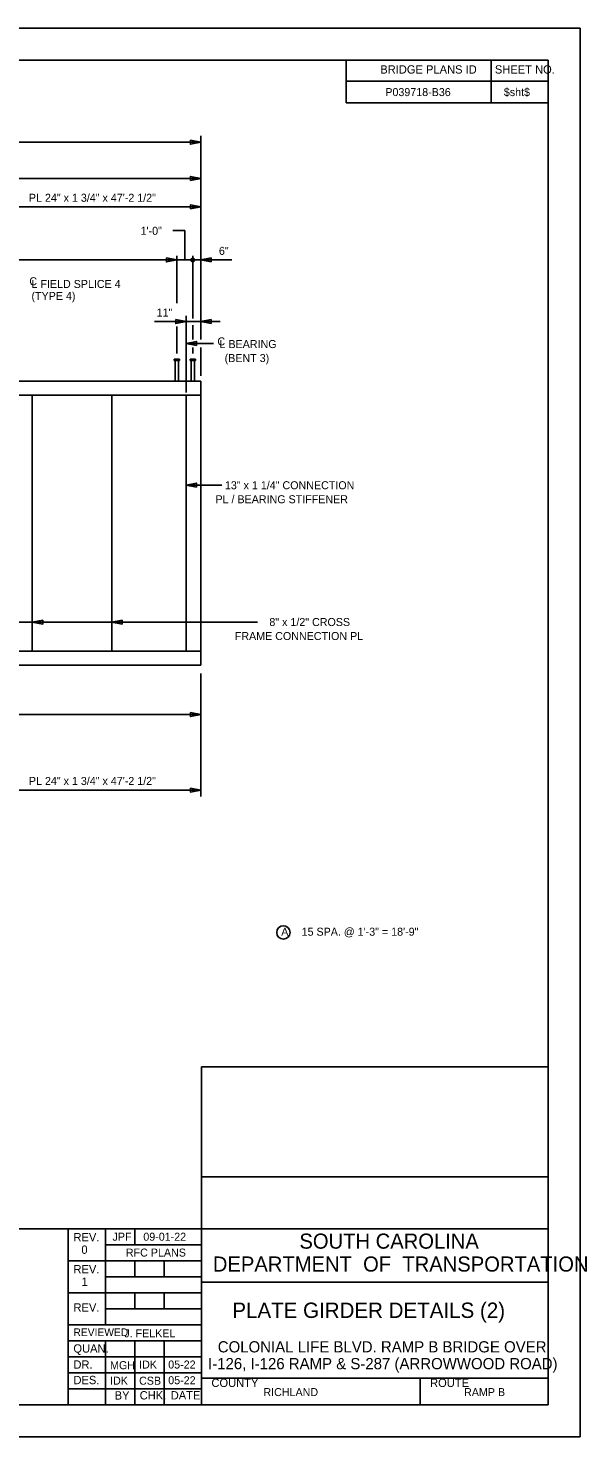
# Model space of a CAD drawing. Extents: x -305 to -161, y -187 to -99.
# Drawn here: x -195.7 to -160.8, y -187.5 to -99.5 of the extents above; entities that cross this region are included whole.
import ezdxf

# ---------------------------------------------------------------- set-up
doc = ezdxf.new("R2010")
doc.units = 0
for name, color, linetype in [('BR_AUTO DIMENSION', 7, 'Continuous'), ('BR_BORDER LINES', 7, 'Continuous'), ('BR_CENTER LINES', 7, 'Continuous'), ('BR_STRUCTURAL STEEL', 7, 'Continuous'), ('BR_TEXT', 7, 'Continuous'), ('Default', 7, 'Continuous'), ('Level 31', 7, 'Continuous')]:
    doc.layers.add(name, color=color, linetype=linetype)

msp = doc.modelspace()

# ---------------------------------------------------------------- linework, layer by layer
at = {"layer": 'BR_AUTO DIMENSION'}
for p, q in [((-184.885, -118.929), (-184.885, -106.206)), ((-284.516, -106.618), (-184.885, -106.618)), ((-231.124, -108.876), (-184.885, -108.876)), ((-184.885, -110.653), (-197.374, -110.653)), ((-225.281, -113.971), (-186.385, -113.971)), ((-186.385, -116.668), (-186.385, -113.71)), ((-182.932, -113.971), (-186.385, -113.971)), ((-185.385, -117.621), (-185.385, -113.71)), ((-187.771, -117.821), (-183.662, -117.821)), ((-186.385, -119.81), (-186.385, -118.124)), ((-185.385, -118.929), (-185.385, -118.048)), ((-185.802, -119.183), (-184.078, -119.183)), ((-185.385, -119.81), (-185.385, -119.447)), ((-184.885, -121.218), (-184.885, -119.447)), ((-185.802, -128.037), (-183.576, -128.037)), ((-225.147, -136.601), (-181.335, -136.601)), ((-184.885, -139.795), (-184.885, -147.486)), ((-184.885, -142.367), (-219.624, -142.367)), ((-197.374, -147.085), (-184.885, -147.085))]:
    msp.add_line(p, q, dxfattribs=at)
for points in [[(-185.535, -106.493), (-184.885, -106.618), (-185.535, -106.743)], [(-185.535, -109.001), (-184.885, -108.876), (-185.535, -108.751)], [(-185.535, -110.778), (-184.885, -110.653), (-185.535, -110.528)], [(-187.035, -113.846), (-186.385, -113.971), (-187.035, -114.096)], [(-184.235, -114.096), (-184.885, -113.971), (-184.235, -113.846)], [(-186.452, -117.696), (-185.802, -117.821), (-186.452, -117.946)], [(-184.235, -117.946), (-184.885, -117.821), (-184.235, -117.696)], [(-185.152, -119.308), (-185.802, -119.183), (-185.152, -119.058)], [(-185.152, -128.162), (-185.802, -128.037), (-185.152, -127.912)], [(-194.766, -136.726), (-195.416, -136.601), (-194.766, -136.476)], [(-189.803, -136.726), (-190.453, -136.601), (-189.803, -136.476)], [(-185.535, -142.242), (-184.885, -142.367), (-185.535, -142.492)], [(-185.535, -146.96), (-184.885, -147.085), (-185.535, -147.21)]]:
    msp.add_lwpolyline(points, close=True, dxfattribs=at)
msp.add_lwpolyline([(-185.885, -113.971), (-185.885, -112.129), (-186.625, -112.129)], dxfattribs=at)
for centre, radius in [((-185.385, -113.971), 0.111), ((-179.72, -155.982), 0.417)]:
    msp.add_circle(centre, radius, dxfattribs=at)
at = {"layer": 'BR_BORDER LINES'}
for p, q in [((-163.178, -101.489), (-297.843, -101.489)), ((-175.788, -104.156), (-175.788, -101.489)), ((-166.722, -104.156), (-166.722, -101.489)), ((-163.178, -185.489), (-163.178, -101.489)), ((-175.788, -102.808), (-163.178, -102.808)), ((-166.722, -102.808), (-163.178, -102.808)), ((-163.178, -104.156), (-175.788, -104.156)), ((-184.846, -185.489), (-184.846, -164.383)), ((-184.846, -164.383), (-163.178, -164.383)), ((-184.845, -171.242), (-163.178, -171.242)), ((-214.64, -174.489), (-193.18, -174.489)), ((-193.18, -185.489), (-193.18, -174.489)), ((-193.18, -174.489), (-163.178, -174.489)), ((-190.846, -174.489), (-190.846, -180.489)), ((-189.013, -175.489), (-189.013, -174.489)), ((-190.846, -175.489), (-184.846, -175.489)), ((-193.18, -176.489), (-184.846, -176.489)), ((-189.013, -177.489), (-189.013, -176.489)), ((-187.179, -177.489), (-187.179, -176.489)), ((-190.846, -177.489), (-184.846, -177.489)), ((-193.18, -178.489), (-184.846, -178.489)), ((-189.013, -179.489), (-189.013, -178.489)), ((-187.179, -179.489), (-187.179, -178.489)), ((-184.846, -177.822), (-184.846, -177.822)), ((-184.846, -177.823), (-163.178, -177.823)), ((-190.846, -179.489), (-184.846, -179.489)), ((-193.18, -180.489), (-184.846, -180.489)), ((-193.18, -181.489), (-184.846, -181.489)), ((-190.846, -181.489), (-190.846, -185.489)), ((-189.013, -181.489), (-189.013, -185.489)), ((-187.179, -181.489), (-187.179, -185.489)), ((-193.18, -182.489), (-184.846, -182.489)), ((-193.18, -183.489), (-184.846, -183.489)), ((-184.846, -183.823), (-163.178, -183.823)), ((-184.456, -183.823), (-163.178, -183.823)), ((-171.179, -185.489), (-171.179, -183.823)), ((-193.18, -184.489), (-184.846, -184.489)), ((-297.843, -185.489), (-163.178, -185.489))]:
    msp.add_line(p, q, dxfattribs=at)
at = {"layer": 'BR_CENTER LINES'}
msp.add_line((-185.802, -117.463), (-185.802, -122.256), dxfattribs=at)
at = {"layer": 'BR_STRUCTURAL STEEL'}
for p, q in [((-184.885, -121.537), (-197.374, -121.537)), ((-184.885, -121.537), (-184.885, -122.412)), ((-184.885, -122.412), (-284.516, -122.412)), ((-195.416, -138.412), (-195.416, -122.412)), ((-190.453, -138.412), (-190.453, -122.412)), ((-185.802, -122.412), (-185.802, -138.412)), ((-184.885, -122.412), (-184.885, -138.412)), ((-184.885, -138.412), (-284.516, -138.412)), ((-184.885, -138.412), (-184.885, -139.287)), ((-184.885, -139.287), (-197.374, -139.287))]:
    msp.add_line(p, q, dxfattribs=at)
at = {"layer": 'Default'}
for p, q in [((-186.557, -120.162), (-186.557, -120.256)), ((-186.557, -120.162), (-186.213, -120.162)), ((-186.557, -120.256), (-186.213, -120.256)), ((-186.494, -120.256), (-186.494, -121.537)), ((-186.276, -120.256), (-186.276, -121.537)), ((-186.213, -120.162), (-186.213, -120.256)), ((-185.557, -120.162), (-185.557, -120.256)), ((-185.557, -120.162), (-185.213, -120.162)), ((-185.557, -120.256), (-185.213, -120.256)), ((-185.494, -120.256), (-185.494, -121.537)), ((-185.276, -120.256), (-185.276, -121.537)), ((-185.213, -120.162), (-185.213, -120.256))]:
    msp.add_line(p, q, dxfattribs=at)
at = {"layer": 'Level 31'}
msp.add_line((-174.011, -179.583), (-174.011, -179.583), dxfattribs=at)
msp.add_lwpolyline([(-305.176, -187.489), (-161.176, -187.489), (-161.176, -99.489), (-305.176, -99.489)], close=True, dxfattribs=at)

# ---------------------------------------------------------------- texts
at = {"layer": 'BR_AUTO DIMENSION'}
for s, p in [('PL 24" x 1 3/4" x 47\'-2 1/2"', (-195.627, -110.334)), ('1\'-0"', (-188.647, -112.398)), ('6"', (-183.75, -113.652)), ('11"', (-187.644, -117.502)), ('PL 24" x 1 3/4" x 47\'-2 1/2"', (-195.627, -146.766)), ('A', (-179.854, -156.185)), ('15 SPA. @ 1\'-3" = 18\'-9"', (-178.579, -156.185))]:
    msp.add_text(s, height=0.5, rotation=360, dxfattribs=at).set_placement(p)
at = {"layer": 'BR_TEXT'}
for s, height, p in [('BRIDGE PLANS ID', 0.52, (-173.663, -102.327)), ('SHEET NO.', 0.52, (-166.499, -102.327)), ('P039718-B36', 0.5, (-173.348, -103.732)), ('$sht$', 0.5, (-165.939, -103.732)), ('C', 0.5, (-183.843, -119.306)), ('L BEARING', 0.5, (-183.711, -119.473)), ('(BENT 3)', 0.5, (-183.392, -120.348)), ('13" x 1 1/4" CONNECTION ', 0.5, (-183.374, -128.293)), ('PL / BEARING STIFFENER', 0.5, (-183.966, -129.168)), ('8" x 1/2" CROSS ', 0.5, (-180.596, -136.838)), ('FRAME CONNECTION PL', 0.5, (-182.757, -137.713)), ('REV.', 0.52, (-192.841, -175.277)), ('JPF', 0.5, (-190.4, -175.239)), ('09-01-22', 0.5, (-188.475, -175.239)), ('SOUTH CAROLINA', 0.94348, (-178.718, -175.735)), ('0', 0.52, (-192.345, -176.057)), ('RFC PLANS', 0.5, (-189.566, -176.229)), ('REV.', 0.52, (-192.841, -177.277)), ('DEPARTMENT  OF  TRANSPORTATION', 0.94348, (-184.129, -177.166)), ('1', 0.52, (-192.337, -178.057)), ('REV.', 0.52, (-192.841, -179.667)), ('PLATE GIRDER DETAILS (2)', 0.96, (-182.913, -180.063)), ('REVIEWED', 0.48, (-192.843, -181.195)), ('J. FELKEL', 0.5, (-189.664, -181.272)), ('QUAN.', 0.52, (-192.846, -182.229)), ('COLONIAL LIFE BLVD. RAMP B BRIDGE OVER', 0.7, (-183.82, -182.216)), ('DR.', 0.52, (-192.845, -183.235)), ('MGH', 0.5, (-190.555, -183.263)), ('IDK', 0.5, (-188.739, -183.222)), ('05-22', 0.5, (-186.918, -183.222)), ('I-126, I-126 RAMP & S-287 (ARROWWOOD ROAD) ', 0.7, (-184.429, -183.266)), ('DES.', 0.52, (-192.841, -184.2)), ('IDK', 0.5, (-190.555, -184.228)), ('CSB', 0.5, (-188.739, -184.234)), ('05-22', 0.5, (-186.918, -184.203)), ('COUNTY', 0.52, (-184.217, -184.376)), ('ROUTE', 0.52, (-170.55, -184.376)), ('BY', 0.52, (-190.265, -185.161)), ('CHK.', 0.52, (-188.701, -185.156)), ('DATE', 0.52, (-186.761, -185.156)), ('RICHLAND', 0.5, (-180.968, -184.944)), ('RAMP B', 0.5, (-168.424, -184.944))]:
    msp.add_text(s, height=height, dxfattribs=at).set_placement(p)
for s, p in [('C', (-195.601, -115.551)), ('L FIELD SPLICE 4', (-195.466, -115.718)), ('(TYPE 4)', (-195.466, -116.468))]:
    msp.add_text(s, height=0.5, rotation=360, dxfattribs=at).set_placement(p)

doc.saveas('drawing.dxf')
